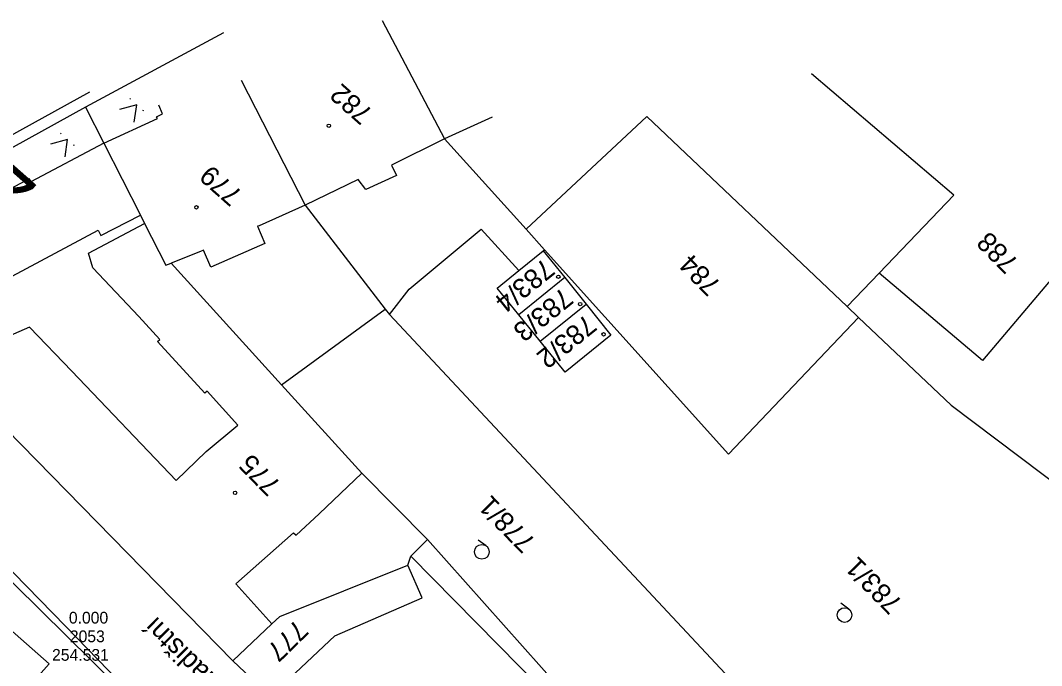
# Model space of a CAD drawing. Extents: x -496688 to -495455, y -1089309 to -1088026.
# Drawn here: x -496512.3 to -496408.1, y -1088100 to -1088034.2 of the extents above; entities that cross this region are included whole.
import ezdxf

# ---------------------------------------------------------------- set-up
doc = ezdxf.new("R2010")
doc.units = 0
for name, color, linetype in [('Vrstva 17', 7, 'Continuous'), ('Vrstva 23', 7, 'Continuous'), ('Vrstva 52', 7, 'Continuous'), ('Vrstva 53', 7, 'Continuous'), ('Vrstva 55', 7, 'Continuous'), ('Vrstva 56', 7, 'Continuous'), ('Vrstva 57', 7, 'Continuous'), ('Vrstva 58', 7, 'Continuous'), ('Vrstva 59', 7, 'Continuous'), ('Vrstva 60', 7, 'Continuous'), ('Vrstva 61', 7, 'Continuous'), ('Vrstva 7', 7, 'Continuous')]:
    doc.layers.add(name, color=color, linetype=linetype)

msp = doc.modelspace()

# ---------------------------------------------------------------- linework, layer by layer
at = {"layer": 'Vrstva 17'}
msp.add_lwpolyline([(-496539.277, -1088065.743), (-496491.754, -1088112.591), (-496473.427, -1088131.659), (-496469.282, -1088135.886)], dxfattribs=at)
at = {"layer": 'Vrstva 23'}
for p, q in [((-496475.36, -1088034.2), (-496468.99, -1088046.29)), ((-496489.76, -1088040.29), (-496483.23, -1088053.04)), ((-496498.39, -1088044.02), (-496497.76, -1088043.73)), ((-496497.76, -1088043.73), (-496498.16, -1088042.85)), ((-496503.75, -1088046.73), (-496498.3, -1088044.22)), ((-496498.3, -1088044.22), (-496498.39, -1088044.02)), ((-496503.75, -1088046.73), (-496511.2, -1088050.65)), ((-496503.75, -1088046.73), (-496500.03, -1088054.06)), ((-496468.99, -1088046.29), (-496474.39, -1088048.97)), ((-496474.39, -1088048.97), (-496473.91, -1088050.01)), ((-496511.36, -1088050.35), (-496516.74, -1088053.18)), ((-496511.2, -1088050.65), (-496511.36, -1088050.35)), ((-496477.79, -1088050.44), (-496483.23, -1088053.04)), ((-496477.03, -1088051.45), (-496477.79, -1088050.44)), ((-496483.23, -1088053.04), (-496487.92, -1088055.14)), ((-496504.06, -1088056.13), (-496500.03, -1088054.06)), ((-496500.03, -1088054.06), (-496499.6, -1088054.9)), ((-496505.34, -1088057.94), (-496499.6, -1088054.9)), ((-496499.6, -1088054.9), (-496497.43, -1088059.17)), ((-496487.92, -1088055.14), (-496488.09, -1088055.2)), ((-496488.09, -1088055.2), (-496487.32, -1088056.95)), ((-496504.34, -1088055.6), (-496504.06, -1088056.13)), ((-496504.89, -1088059.44), (-496505.34, -1088057.94)), ((-496493.9, -1088057.78), (-496496.9, -1088058.96)), ((-496493.6, -1088057.63), (-496493.9, -1088057.78)), ((-496492.84, -1088059.37), (-496493.6, -1088057.63)), ((-496461.41, -1088059.72), (-496458.93, -1088057.71)), ((-496458.93, -1088057.71), (-496456.73, -1088060.44)), ((-496497.43, -1088059.17), (-496496.9, -1088058.96)), ((-496496.9, -1088058.96), (-496485.62, -1088071.37)), ((-496500.19, -1088064.42), (-496504.89, -1088059.44)), ((-496463.62, -1088061.5), (-496461.41, -1088059.72)), ((-496456.73, -1088060.44), (-496461.42, -1088064.22)), ((-496456.73, -1088060.44), (-496454.53, -1088063.16)), ((-496461.42, -1088064.22), (-496463.62, -1088061.5)), ((-496459.23, -1088066.92), (-496454.53, -1088063.16)), ((-496454.53, -1088063.16), (-496452.01, -1088066.3)), ((-496498.05, -1088066.76), (-496500.19, -1088064.42)), ((-496459.23, -1088066.92), (-496461.42, -1088064.22)), ((-496511.33, -1088065.49), (-496519.33, -1088068.95)), ((-496507.02, -1088069.99), (-496511.33, -1088065.49)), ((-496452.01, -1088066.3), (-496456.69, -1088070.07)), ((-496498.27, -1088066.96), (-496498.05, -1088066.76)), ((-496493.45, -1088072.23), (-496498.27, -1088066.96)), ((-496456.69, -1088070.07), (-496459.23, -1088066.92)), ((-496485.62, -1088071.37), (-496477.42, -1088080.39)), ((-496493.23, -1088072.03), (-496493.45, -1088072.23)), ((-496490.07, -1088075.5), (-496493.23, -1088072.03)), ((-496502.91, -1088086.95), (-496513.72, -1088075.89)), ((-496493.33, -1088078.18), (-496490.07, -1088075.5)), ((-496496.38, -1088081.13), (-496493.33, -1088078.18)), ((-496481.79, -1088084.52), (-496477.42, -1088080.39)), ((-496490.3, -1088091.68), (-496484.41, -1088086.46)), ((-496484.41, -1088086.46), (-496484.13, -1088086.72)), ((-496490.59, -1088099.54), (-496502.91, -1088086.95)), ((-496472.74, -1088089.78), (-496472.42, -1088088.85)), ((-496472.42, -1088088.85), (-496457.09, -1088104.41)), ((-496471.27, -1088093.11), (-496472.74, -1088089.78)), ((-496486.61, -1088095.77), (-496490.3, -1088091.68)), ((-496480.19, -1088096.97), (-496471.27, -1088093.11)), ((-496490.59, -1088099.54), (-496486.61, -1088095.77)), ((-496486.4, -1088102.8), (-496480.19, -1088096.97))]:
    msp.add_line(p, q, dxfattribs=at)
msp.add_lwpolyline([(-496509.345, -1088099.823), (-496516.555, -1088107.946), (-496537.348, -1088089.673), (-496530.148, -1088081.499), (-496509.345, -1088099.823)], dxfattribs=at)
at = {"layer": 'Vrstva 52'}
for p, q in [((-496473.91, -1088050.01), (-496477.03, -1088051.45)), ((-496516.39, -1088062), (-496504.34, -1088055.6)), ((-496487.32, -1088056.95), (-496492.84, -1088059.37)), ((-496507.02, -1088069.99), (-496496.38, -1088081.13)), ((-496484.13, -1088086.72), (-496481.79, -1088084.52))]:
    msp.add_line(p, q, dxfattribs=at)
at = {"layer": 'Vrstva 53'}
msp.add_lwpolyline([(-496539.03, -1088065.6), (-496535.97, -1088067.83), (-496531.62, -1088071.46), (-496507.63, -1088096.03), (-496458.59, -1088146.6), (-496452.94, -1088142.96), (-496452.25, -1088138.8), (-496443.22, -1088147.27), (-496395.64, -1088185.72), (-496395.1, -1088185.29), (-496369.57, -1088204.88), (-496360, -1088212.22), (-496349.3, -1088220.43), (-496330.37, -1088232.05), (-496312.02, -1088243.31), (-496311.81, -1088243.59), (-496302.57, -1088250.38)], dxfattribs=at)
at = {"layer": 'Vrstva 55'}
for p, q in [((-496491.56, -1088035.46), (-496505.64, -1088043.04)), ((-496505.64, -1088043.04), (-496527.61, -1088055.16)), ((-496505.64, -1088043.04), (-496503.75, -1088046.73)), ((-496448.33, -1088044.01), (-496460.66, -1088055.5)), ((-496427.9, -1088063.4), (-496448.33, -1088044.01)), ((-496468.99, -1088046.29), (-496460.66, -1088055.5)), ((-496483.23, -1088053.04), (-496475.05, -1088063.65)), ((-496472.61, -1088061.62), (-496465.26, -1088055.5)), ((-496465.26, -1088055.5), (-496461.41, -1088059.72)), ((-496460.66, -1088055.5), (-496458.78, -1088057.6)), ((-496458.93, -1088057.71), (-496458.78, -1088057.6)), ((-496458.78, -1088057.6), (-496440.01, -1088078.44)), ((-496424.63, -1088059.99), (-496427.9, -1088063.4)), ((-496414.08, -1088068.89), (-496424.63, -1088059.99)), ((-496406.22, -1088059.61), (-496414.08, -1088068.89)), ((-496474.62, -1088064.21), (-496472.61, -1088061.62)), ((-496427.9, -1088063.4), (-496426.74, -1088064.5)), ((-496485.62, -1088071.37), (-496475.05, -1088063.65)), ((-496475.05, -1088063.65), (-496474.62, -1088064.21)), ((-496432.83, -1088108.84), (-496474.62, -1088064.21)), ((-496440.01, -1088078.44), (-496426.74, -1088064.5)), ((-496426.74, -1088064.5), (-496417.3, -1088073.45)), ((-496417.3, -1088073.45), (-496391.63, -1088092.77)), ((-496477.42, -1088080.39), (-496470.72, -1088087.17)), ((-496472.42, -1088088.85), (-496470.72, -1088087.17)), ((-496470.72, -1088087.17), (-496442.81, -1088118.48)), ((-496485.8, -1088095), (-496472.74, -1088089.78)), ((-496486.61, -1088095.77), (-496485.8, -1088095)), ((-496486.76, -1088103.13), (-496490.59, -1088099.54))]:
    msp.add_line(p, q, dxfattribs=at)
at = {"layer": 'Vrstva 56'}
for p, q in [((-496417, -1088052.03), (-496431.53, -1088039.64)), ((-496516.17, -1088047.52), (-496505.18, -1088041.49)), ((-496464.13, -1088044.07), (-496468.99, -1088046.29)), ((-496417, -1088052.03), (-496424.63, -1088059.99))]:
    msp.add_line(p, q, dxfattribs=at)
at = {"layer": 'Vrstva 58'}
for p, q in [((-496501.043, -1088042.246), (-496501.118, -1088042.18)), ((-496499.694, -1088043.438), (-496499.769, -1088043.372)), ((-496508.114, -1088045.783), (-496508.189, -1088045.717)), ((-496506.765, -1088046.975), (-496506.84, -1088046.909)), ((-496464.742, -1088087.804), (-496465.548, -1088087.213)), ((-496427.726, -1088094.253), (-496428.532, -1088093.662))]:
    msp.add_line(p, q, dxfattribs=at)
for points in [[(-496500.651, -1088044.595), (-496500.406, -1088042.809), (-496502.149, -1088043.27)], [(-496507.722, -1088048.132), (-496507.477, -1088046.346), (-496509.22, -1088046.807)]]:
    msp.add_lwpolyline(points, dxfattribs=at)
for centre in [(-496465.185, -1088088.409), (-496428.169, -1088094.858)]:
    msp.add_circle(centre, 0.75, dxfattribs=at)
at = {"layer": 'Vrstva 59'}
for centre in [(-496480.798, -1088044.943), (-496494.315, -1088053.265), (-496457.376, -1088060.346), (-496455.152, -1088063.14), (-496452.757, -1088066.219), (-496490.364, -1088082.393)]:
    msp.add_circle(centre, 0.175, dxfattribs=at)
at = {"layer": 'Vrstva 60'}
for p, q in [((-496507.63, -1088096.03), (-496507.63, -1088096.03)), ((-496507.63, -1088096.03), (-496507.63, -1088096.03)), ((-496509.345, -1088099.823), (-496509.345, -1088099.823)), ((-496509.345, -1088099.823), (-496509.345, -1088099.823))]:
    msp.add_line(p, q, dxfattribs=at)

# ---------------------------------------------------------------- texts
at = {"layer": 'Vrstva 57'}
for s, rotation, p in [('782', 138.46319, (-496476.188, -1088043.481)), ('779', 138.46319, (-496489.497, -1088051.803)), ('788', 134.37899, (-496410.299, -1088058.802)), ('784', 134.37899, (-496440.661, -1088061.09)), ('783/4', 218.85337, (-496458.817, -1088058.389)), ('783/3', 218.85337, (-496456.936, -1088061.355)), ('783/2', 218.85337, (-496454.541, -1088064.092)), ('775', 134.37899, (-496485.579, -1088081.48)), ('778/1', 134.37899, (-496459.585, -1088087.305)), ('783/1', 134.37899, (-496422.153, -1088093.546)), ('Skladištní', 135.18517, (-496490.248, -1088103.049)), ('777', 224.48692, (-496484.124, -1088095.212))]:
    msp.add_text(s, height=2, rotation=rotation, dxfattribs=at).set_placement(p)
at = {"layer": 'Vrstva 60'}
msp.add_text('2053', height=1.2, dxfattribs=at).set_placement((-496507.23, -1088097.63))
msp.add_text('2053', height=1.2, dxfattribs=at).set_placement((-496507.23, -1088097.63))
at = {"layer": 'Vrstva 61'}
for s, p in [('0.000', (-496507.33, -1088095.73)), ('0.000', (-496507.33, -1088095.73)), ('254.531', (-496509.045, -1088099.523)), ('254.531', (-496509.045, -1088099.523))]:
    msp.add_text(s, height=1.2, dxfattribs=at).set_placement(p)
at = {"layer": 'Vrstva 7'}
msp.add_text('290.4', height=6, rotation=138.5846, dxfattribs=at).set_placement((-496510.343, -1088051.258))

doc.saveas('drawing.dxf')
